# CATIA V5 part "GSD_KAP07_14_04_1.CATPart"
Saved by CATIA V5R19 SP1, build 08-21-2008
Part number: GSD_KAP07_14_04
Definition: Beispielmodell für die Funktion Formverrundung / Shape Fillet.
Description: CATIA V5 Flächenmodellierung  Copyright (c) 2009 Maik Hertha IT Consultants
Bounding box of the stored display mesh (mm): x -35.67 to 36.196, y -27.277 to 36.171, z 10 to 43.734
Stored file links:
  \GSD_BUCH_UEBUNG\GSD_KAP07_14_04_1.CATPart
  \XV5_ABNAHME_1.0\XV5_BLEND_FILLET_01.CATPart
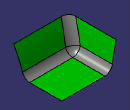
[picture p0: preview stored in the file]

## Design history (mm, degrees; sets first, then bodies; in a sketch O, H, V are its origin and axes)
AxisSystem1 "Absolute Axis System": origin (0, 0, 0), X (1, 0, 0), Y (0, 1, 0), Z (0, 0, 1)
Set1 "Basis_Flaechen"
  Plane1: type Equation, A 0, B 0, C 1, Length 10
  Point1: type OnPlane, Support Plane1, Direction (1, 0, 0), H 10, V -10
  Plane2: type Equation, A 1, B 0, C 0, Length 10
  Plane3: type Equation, A 0, B 1, C 0, Length 10
  Sketch1 on Plane1, origin (10, -10, 10), H (0, 1, 0), V (-1, 0, 0)
    line L1 (-21.1511, 42.5859) -> (46.1715, 42.5859)
    line L2 (46.1715, 42.5859) -> (46.1715, -26.1963)
    line L3 (46.1715, -26.1963) -> (-21.1511, -26.1963)
    line L4 (-21.1511, -26.1963) -> (-21.1511, 42.5859)
    curve C1
    horizontal: L1 H, L3 H
    vertical: L2 V, L4 V
  Sketch2 on Plane2, origin (10, -10, 10), H (0, 1, 0), V (0, 0, 1)
    spline S1 through (-17.2769, 32.8665) (-4.648, 3.9293) (1.0925, -31.1464)
    curve C1
  Split1: ToCut Plane1, Cutting Sketch1.C1
  Extrude1: Lim1 26, Lim2 46, Element1 Sketch2.C1, Direction Plane2
  Sketch3 on Plane3, origin (10, 10, 10), H (-1, 0, 0), V (0, 0, 1)
    spline S1 through (36.9445, -32.1117) (38.7219, -4.676) (45.6699, 33.734)
    curve C1
  Extrude2: Lim1 26, Lim2 46, Element1 Sketch3.C1, Direction Plane3
Set2 "Formverrundung"
  DatumSurface1 to DatumSurface3: linked copy from another document
  Fillet1: type BiTangent, Element1 DatumSurface2, Element2 DatumSurface3, Radius 10
  Fillet2: type BiTangent, Element1 Fillet1, Element2 DatumSurface1, Radius 10
Body1 (main body)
